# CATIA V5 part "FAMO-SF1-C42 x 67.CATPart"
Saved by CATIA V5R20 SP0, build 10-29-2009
Part number: FAMO-SF1-C42 x 67
Definition: NONE
Nomenclature: FAMO-SF1-C42 x 67
Source: Unknown
Description: FAMO-SF1-C42 x 67
Bounding box of the stored display mesh (mm): x -37 to 30, y -31.5 to 31.5, z -31.5 to 31.5
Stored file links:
  C:\Users\Utente\Desktop\IO LAVORO\3D X SITO CF\X SITO\FAMO\FAMO-SF1-C42 x 67.CATPart

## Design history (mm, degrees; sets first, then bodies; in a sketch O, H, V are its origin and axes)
Body1 "FAMO-SF1-C42 x 67" (main body)
  Solid1: solid without history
